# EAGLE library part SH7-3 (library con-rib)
RIBBON CABLE CONNECTOR Flachstecker / Faston
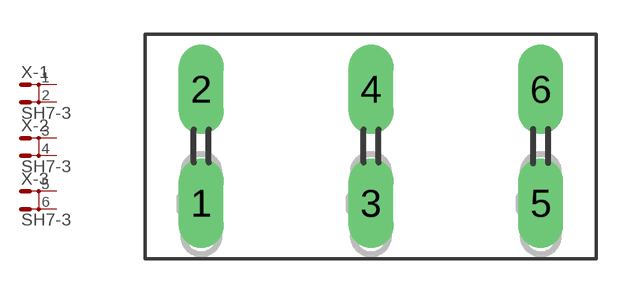
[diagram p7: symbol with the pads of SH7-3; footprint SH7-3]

Designator prefix X; gates -1=MD -2=MD -3=MD

## SH7-3  [SH7-3]
1  -1:1  pas
2  -1:2  pas
3  -2:1  pas
4  -2:2  pas
5  -3:1  pas
6  -3:2  pas

## Footprint SH7-3 (pad centres in mm)
RIBBON CABLE CONNECTOR Flachstecker / Faston
drill 1.321 long: 1 -7.493,-2.515; 2 -7.493,2.515; 3 0,-2.515; 4 0,2.515; 5 7.493,-2.515; 6 7.493,2.515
